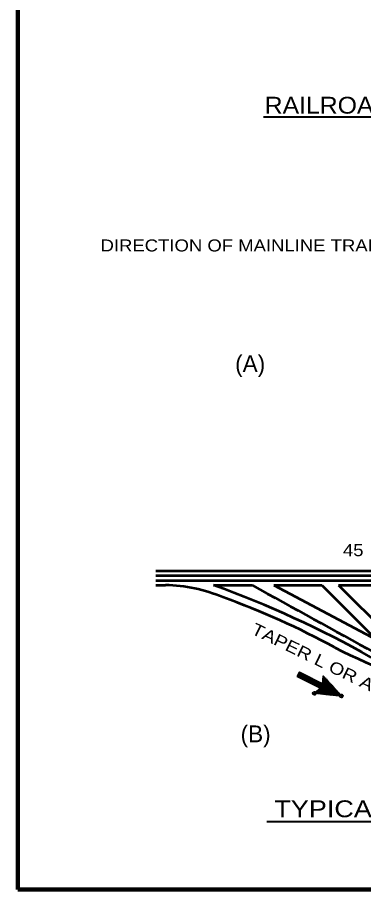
# Model space of a CAD drawing. Extents: x -96 to 617, y -65 to 388.
# Drawn here: x -47.9 to 24.1, y -55.4 to 126.1 of the extents above; entities that cross this region are included whole.
import ezdxf
from ezdxf.enums import TextEntityAlignment as Align

# ---------------------------------------------------------------- set-up
doc = ezdxf.new("R2010")
doc.units = 0
doc.header["$PDMODE"] = 32
doc.header["$PDSIZE"] = 0.5
doc.layers.add('1', color=7, linetype='Continuous', lineweight=53)

msp = doc.modelspace()

# ---------------------------------------------------------------- linework, layer by layer
at = {"layer": '1', "lineweight": 40}
for p, q in [((3.249, 105.393), (88.592, 105.393)), ((3.977, -41.268), (135.772, -41.268))]:
    msp.add_line(p, q, dxfattribs=at)
at = {"layer": '1'}
for p, q in [((-19.121, 10.942), (168.879, 10.942)), ((-19.121, 9.942), (168.879, 9.942)), ((-19.121, 8.942), (168.879, 8.942)), ((-19.121, 7.942), (-17.121, 7.942)), ((-7.121, 7.942), (0.879, 7.942)), ((5.379, 7.942), (15.379, 7.942)), ((5.379, 7.942), (26.693, -3.371)), ((15.379, 7.942), (26.693, -3.371)), ((18.879, 7.942), (26.879, 7.942)), ((18.879, 7.942), (32.314, -5.492))]:
    msp.add_line(p, q, dxfattribs=at)
at = {"layer": '1', "lineweight": 35}
for p, q in [((10.377, -10.879), (10.466, -11.151)), ((10.468, -10.698), (10.647, -11.242)), ((10.514, -10.608), (10.737, -11.288)), ((10.605, -10.427), (10.918, -11.379)), ((10.651, -10.337), (11.008, -11.425)), ((10.696, -10.246), (11.099, -11.471)), ((10.742, -10.156), (15.531, -12.577)), ((10.832, -10.202), (11.279, -11.562)), ((10.923, -10.247), (11.37, -11.608)), ((11.104, -10.339), (11.55, -11.699)), ((11.194, -10.384), (11.641, -11.745)), ((11.375, -10.476), (11.822, -11.836)), ((11.465, -10.521), (11.912, -11.882)), ((11.555, -10.567), (12.002, -11.927)), ((11.736, -10.658), (12.183, -12.019)), ((11.826, -10.704), (12.273, -12.064)), ((12.007, -10.795), (12.454, -12.156)), ((12.098, -10.841), (12.544, -12.201)), ((12.188, -10.887), (12.635, -12.247)), ((10.331, -10.969), (10.376, -11.105)), ((12.369, -10.978), (12.816, -12.338)), ((12.459, -11.024), (12.906, -12.384)), ((12.64, -11.115), (13.087, -12.475)), ((12.73, -11.161), (13.177, -12.521)), ((12.911, -11.252), (13.358, -12.612)), ((13.001, -11.298), (13.448, -12.658)), ((13.091, -11.343), (13.538, -12.704)), ((13.272, -11.435), (13.719, -12.795)), ((13.363, -11.48), (13.809, -12.841)), ((13.543, -11.572), (13.99, -12.932)), ((13.634, -11.617), (14.081, -12.978)), ((13.724, -11.663), (14.171, -13.024)), ((13.905, -11.755), (14.352, -13.115)), ((13.995, -11.8), (14.442, -13.16)), ((14.176, -11.891), (14.623, -13.252)), ((14.266, -11.937), (14.713, -13.298)), ((14.357, -11.983), (14.803, -13.343)), ((14.537, -12.074), (14.984, -13.435)), ((14.628, -12.12), (15.477, -14.705)), ((14.808, -12.211), (15.657, -14.796)), ((14.899, -12.257), (15.793, -14.751)), ((15.079, -12.348), (15.884, -14.797)), ((15.17, -12.394), (15.974, -14.843)), ((15.26, -12.44), (16.11, -14.798)), ((15.441, -12.531), (16.201, -14.844)), ((15.531, -12.577), (16.337, -14.799)), ((15.578, -12.26), (16.427, -14.845)), ((15.579, -12.033), (16.517, -14.89)), ((15.58, -11.807), (16.653, -14.845)), ((15.627, -11.49), (16.744, -14.891)), ((15.628, -11.264), (16.834, -14.937)), ((15.629, -11.037), (16.97, -14.892)), ((15.809, -11.129), (17.061, -14.938)), ((15.944, -11.311), (17.197, -14.893)), ((16.125, -11.402), (17.287, -14.939)), ((16.351, -11.629), (17.377, -14.984)), ((16.485, -11.811), (17.513, -14.94)), ((16.621, -11.993), (17.604, -14.986)), ((16.756, -12.174), (17.74, -14.941)), ((16.981, -12.402), (17.83, -14.986)), ((17.116, -12.583), (17.921, -15.032)), ((17.297, -12.675), (18.057, -14.987)), ((13.893, -14.471), (13.938, -14.607)), ((14.029, -14.427), (14.074, -14.563)), ((14.075, -14.336), (14.164, -14.608)), ((14.211, -14.292), (14.3, -14.564)), ((14.256, -14.201), (14.39, -14.609)), ((14.302, -14.111), (14.481, -14.655)), ((14.438, -14.066), (14.617, -14.61)), ((14.484, -13.976), (14.707, -14.656)), ((14.62, -13.931), (14.843, -14.611)), ((14.665, -13.841), (14.934, -14.657)), ((14.711, -13.75), (15.024, -14.703)), ((14.847, -13.706), (15.16, -14.658)), ((14.893, -13.615), (15.25, -14.704)), ((15.029, -13.571), (15.341, -14.749)), ((17.522, -12.902), (18.147, -15.033)), ((17.657, -13.084), (18.283, -14.988)), ((17.792, -13.266), (18.373, -15.034)), ((17.927, -13.447), (18.464, -15.08)), ((18.153, -13.675), (18.6, -15.035)), ((18.288, -13.856), (18.69, -15.081)), ((18.469, -13.948), (18.78, -15.127)), ((18.604, -14.13), (18.916, -15.082)), ((18.829, -14.357), (19.007, -15.127)), ((18.964, -14.539), (19.143, -15.083)), ((19.099, -14.72), (19.233, -15.128)), ((19.234, -14.902), (19.324, -15.174))]:
    msp.add_line(p, q, dxfattribs=at)
at = {"layer": '1', "lineweight": 158}
msp.add_line((611.853, -55.407), (-47.814, -55.407), dxfattribs=at)
msp.add_lwpolyline([(611.853, 383.009), (-47.897, 382.926), (-47.814, -55.407)], dxfattribs=at)
at = {"layer": '1', "lineweight": 35}
msp.add_lwpolyline([(15.075, -13.48), (10.285, -11.06), (10.742, -10.156)], dxfattribs=at)
msp.add_lwpolyline([(19.55, -15.175), (13.847, -14.562), (15.075, -13.48), (10.285, -11.06), (10.742, -10.156), (15.531, -12.577), (15.674, -10.947)], close=True, dxfattribs=at)
at = {"layer": '1'}
for centre, radius, start, end in [((-17.75, -24.609), 32.558, 67.32194, 88.89255), ((-80.833, -196.113), 216.961, 60.60058, 70.13846), ((2132.222, 3850.287), 4393.885, 240.98294, 241.36318), ((-60.2, -148.044), 163.034, 61.29677, 70.28331), ((72.425, 100.59), 118.784, 242.78447, 256.33579)]:
    msp.add_arc(centre, radius, start, end, dxfattribs=at)
for p in [(13.847, -14.562), (19.46, -15.129)]:
    msp.add_point(p, dxfattribs=at)

# ---------------------------------------------------------------- texts
for s, height, width, p in [('RAILROAD-HIGHWAY CROSSINGS', 3.5, 1.1, (45.994, 106.091)), ('DIRECTION OF MAINLINE TRAFFIC', 2.5, 1.15, (1.415, 77.402)), ('45', 2.5, 1.15, (21.908, 13.981)), ('TYPICAL LANE SHUNT     UNDIVIDED HIGHWAY', 3.5, 1.2, (69.318, -40.346))]:
    msp.add_text(s, height=height, dxfattribs=dict(at, width=width)).set_placement(p, align=Align.CENTER)
for s, p in [('(A)', (0.485, 52.307)), ('(B)', (1.621, -24.756))]:
    msp.add_text(s, height=3.5, dxfattribs=at).set_placement(p, align=Align.CENTER)
at = {"layer": '1', "width": 1.2}
msp.add_text('TAPER L OR AS SPECIFIED', height=2.5, rotation=333.998, dxfattribs=at).set_placement((24.173, -13.593), align=Align.CENTER)

doc.saveas('drawing.dxf')
